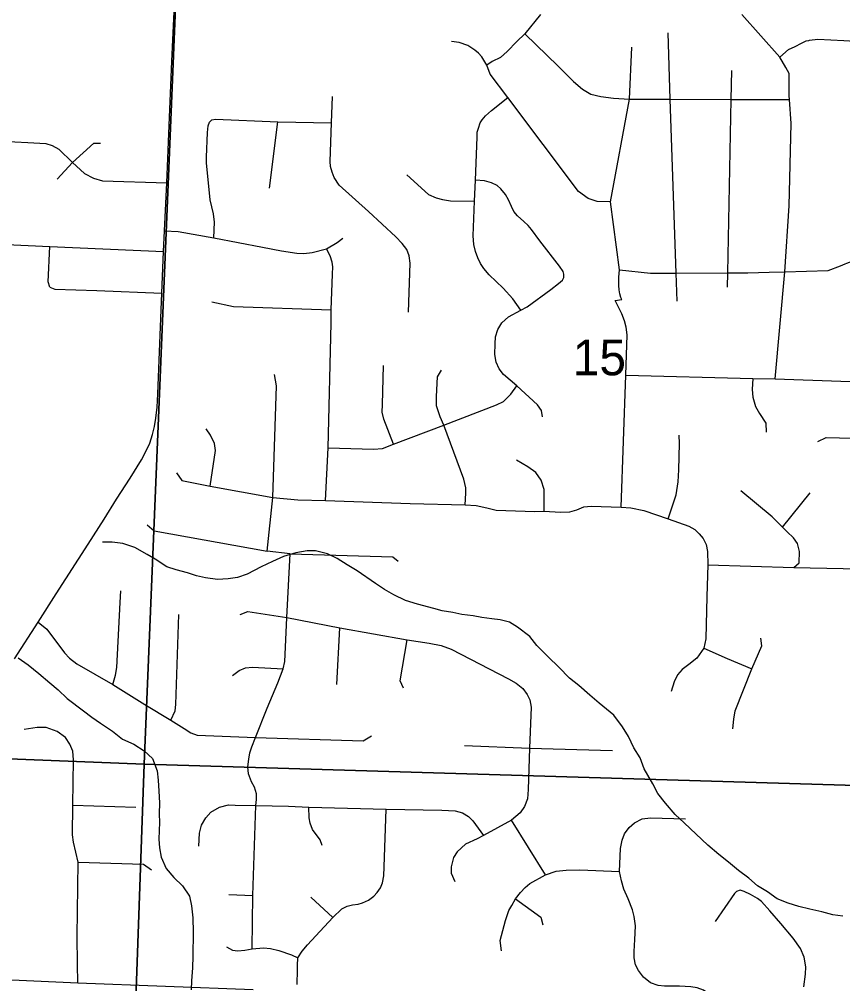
# Model space of a CAD drawing. Extents: x 0 to 34, y 0 to 22.
# Drawn here: x 6.135 to 7.099, y 17.654 to 18.784 of the extents above; entities that cross this region are included whole.
import ezdxf

# ---------------------------------------------------------------- set-up
doc = ezdxf.new("R2010")
doc.units = 0
for name, color, linetype in [('GM_X_Corporation', 7, 'Continuous'), ('GM_X_Minor_River', 7, 'Continuous'), ('GM_X_Section_Text', 7, 'Continuous'), ('GM_X_State_Route', 7, 'Continuous'), ('GM_X_Township_Road', 7, 'Continuous')]:
    doc.layers.add(name, color=color, linetype=linetype)

msp = doc.modelspace()

# ---------------------------------------------------------------- linework, layer by layer
at = {"layer": 'GM_X_Corporation'}
for points in [[(5.2829, 18.9603), (6.3228, 18.9214), (6.2808, 17.9117), (5.2412, 17.9526)], [(6.3228, 18.9214), (7.3448, 18.8879), (7.31, 17.8806), (6.2808, 17.9117)], [(5.2412, 17.9526), (6.2808, 17.9117), (6.2453, 16.9071), (5.2034, 16.9522)], [(7.31, 17.8806), (7.2756, 16.8704), (6.2453, 16.9071), (6.2808, 17.9117)]]:
    msp.add_lwpolyline(points, close=True, dxfattribs=at)
at = {"layer": 'GM_X_Minor_River'}
for points in [[(7.0991, 17.7334), (7.0873, 17.7352), (7.0743, 17.7384), (7.0603, 17.7416), (7.0473, 17.7449), (7.0348, 17.7489), (7.0222, 17.7536), (7.0107, 17.7618), (6.9992, 17.7689), (6.9888, 17.7779), (6.9766, 17.7868), (6.9651, 17.7969), (6.9536, 17.8059), (6.9409, 17.8167), (6.9132, 17.8429), (6.9028, 17.8527), (6.8913, 17.8658), (6.8824, 17.8771), (6.8766, 17.8884), (6.8665, 17.9061), (6.8617, 17.919), (6.8544, 17.9306), (6.8481, 17.9438), (6.8408, 17.9555), (6.8307, 17.969), (6.8138, 17.9829), (6.8027, 17.9926), (6.79, 18.0038), (6.7789, 18.0124), (6.7666, 18.0251), (6.7539, 18.0375), (6.7408, 18.0506), (6.7323, 18.0611), (6.7182, 18.072), (6.7086, 18.0779), (6.6976, 18.0808), (6.6881, 18.0818), (6.6763, 18.0835), (6.666, 18.0853), (6.6527, 18.087), (6.6421, 18.0891), (6.6299, 18.0912), (6.62, 18.0938), (6.6009, 18.0992), (6.5869, 18.1035), (6.5731, 18.1098), (6.5624, 18.1161), (6.5517, 18.1232), (6.5302, 18.1381), (6.5184, 18.1451), (6.5069, 18.1526), (6.4954, 18.1581), (6.4814, 18.1617), (6.4719, 18.1616), (6.4586, 18.1591), (6.4439, 18.1547), (6.4311, 18.1489), (6.4179, 18.1426), (6.4013, 18.134), (6.39, 18.1304), (6.3794, 18.1288), (6.3669, 18.1278), (6.3528, 18.1299), (6.3422, 18.1324), (6.3315, 18.1357), (6.3185, 18.1393), (6.3075, 18.1429), (6.2937, 18.1519), (6.2842, 18.1574), (6.27, 18.1656), (6.2559, 18.17), (6.2434, 18.1717), (6.232, 18.1715)], [(6.1333, 18.036), (6.1452, 18.0278), (6.1574, 18.0177), (6.1705, 18.0069), (6.1801, 17.9987), (6.1905, 17.9886), (6.21, 17.974), (6.2196, 17.9665), (6.2296, 17.9598), (6.2437, 17.9502), (6.2556, 17.9408), (6.2686, 17.9349), (6.2808, 17.9271), (6.2908, 17.9182), (6.2959, 17.9038), (6.2972, 17.8928), (6.2982, 17.8799), (6.2987, 17.8662), (6.2985, 17.8533), (6.2987, 17.8434), (6.2984, 17.8339), (6.2982, 17.8236), (6.2987, 17.8134), (6.3007, 17.8028), (6.3066, 17.7892), (6.3155, 17.7787), (6.3258, 17.7689), (6.334, 17.7569), (6.3364, 17.7455), (6.3377, 17.7315), (6.3383, 17.7148), (6.338, 17.6867)], [(6.338, 17.6867), (6.3374, 17.673), (6.3361, 17.6578), (6.3358, 17.6471)]]:
    msp.add_lwpolyline(points, dxfattribs=at)
at = {"layer": 'GM_X_State_Route'}
for points in [[(6.1291, 18.0348), (6.1567, 18.0779), (6.178, 18.1111), (6.2153, 18.1692), (6.2339, 18.1988), (6.2486, 18.2219), (6.2643, 18.2465), (6.2777, 18.2683), (6.2832, 18.2787), (6.2874, 18.2878), (6.2906, 18.2978), (6.293, 18.3073), (6.2946, 18.3168), (6.2961, 18.33), (6.2969, 18.3454), (6.2989, 18.3945), (6.3014, 18.4636), (6.3035, 18.5124), (6.3046, 18.5364), (6.3073, 18.5928), (6.3103, 18.6597), (6.3132, 18.7351), (6.3169, 18.8101)], [(6.048, 17.6624), (6.203, 17.6552), (6.4083, 17.6474)]]:
    msp.add_lwpolyline(points, dxfattribs=at)
at = {"layer": 'GM_X_Township_Road'}
for p, q in [((6.4276, 18.5865), (6.4375, 18.664)), ((7.0284, 18.1892), (7.0608, 18.2296)), ((6.4518, 18.1579), (6.425, 18.1613)), ((6.5065, 18.0049), (6.5098, 18.0715)), ((6.1973, 17.8635), (6.2712, 17.8613)), ((6.7507, 17.7821), (6.711, 17.8459)), ((6.3801, 17.759), (6.4082, 17.7576)), ((6.5017, 17.732), (6.476, 17.7559)), ((6.4604, 17.6705), (6.4605, 17.6756)), ((6.4599, 17.6534), (6.4604, 17.6705))]:
    msp.add_line(p, q, dxfattribs=at)
for points in [[(6.7451, 18.7901), (6.7265, 18.7673), (6.7173, 18.7581), (6.7059, 18.7465), (6.6982, 18.7396), (6.6882, 18.7348), (6.682, 18.7304)], [(7.0196, 18.3629), (7.031, 18.4885), (7.036, 18.5658), (7.0384, 18.6622), (7.0364, 18.6902), (7.0361, 18.6946), (7.0363, 18.7208), (7.0321, 18.7277), (7.0253, 18.7401), (6.9808, 18.7898)], [(6.827, 18.5704), (6.8112, 18.5708), (6.8008, 18.5745), (6.7896, 18.5825), (6.7067, 18.6926), (6.6861, 18.7202), (6.682, 18.7304), (6.6761, 18.7402), (6.6724, 18.7446), (6.668, 18.7483), (6.6599, 18.7536), (6.6497, 18.7571), (6.6407, 18.7583)], [(6.7265, 18.7673), (6.7658, 18.7295), (6.7835, 18.7114), (6.794, 18.7026), (6.804, 18.6965), (6.8155, 18.6937), (6.8303, 18.692), (6.8492, 18.6909), (6.8965, 18.6907), (6.9677, 18.6905), (7.0364, 18.6902)], [(6.8939, 18.7684), (6.8965, 18.6907), (6.9034, 18.487), (6.9045, 18.454)], [(7.0253, 18.7401), (7.0355, 18.749), (7.0431, 18.7523), (7.0507, 18.7563), (7.0561, 18.7592), (7.059, 18.7596), (7.06, 18.7597)], [(7.06, 18.7597), (7.0697, 18.7609), (7.1, 18.7596), (7.1661, 18.7557), (7.1991, 18.7493)], [(6.8393, 18.2126), (6.8449, 18.3673), (6.8464, 18.4147), (6.8453, 18.4237), (6.8434, 18.431), (6.8401, 18.4391), (6.8322, 18.4549), (6.8401, 18.4559), (6.8392, 18.4583), (6.838, 18.4625), (6.8371, 18.4672), (6.8366, 18.4724), (6.8365, 18.4782), (6.8368, 18.4822), (6.8376, 18.4909), (6.827, 18.5704), (6.8492, 18.6909), (6.852, 18.7517)], [(6.9684, 18.7243), (6.9677, 18.6905), (6.964, 18.4873), (6.9637, 18.4704)], [(6.5905, 18.4413), (6.5922, 18.4984), (6.5912, 18.507), (6.5883, 18.5144), (6.5831, 18.5216), (6.5757, 18.5293), (6.5435, 18.5592), (6.5092, 18.5901), (6.5034, 18.5989), (6.5009, 18.6051), (6.4992, 18.6118), (6.4988, 18.6176), (6.5001, 18.6631), (6.5015, 18.6938)], [(6.722, 18.4436), (6.7126, 18.4569), (6.7014, 18.4691), (6.685, 18.4849), (6.6786, 18.4922), (6.6748, 18.498), (6.6715, 18.5049), (6.6687, 18.5122), (6.6669, 18.5206), (6.6662, 18.5306), (6.6676, 18.5712), (6.669, 18.596), (6.6707, 18.6461), (6.6709, 18.6522), (6.6722, 18.6568), (6.6743, 18.6628), (6.6768, 18.6665), (6.6807, 18.6713), (6.6876, 18.6776), (6.7067, 18.6926)], [(6.3624, 18.5284), (6.3631, 18.5467), (6.362, 18.5565), (6.3582, 18.5726), (6.3538, 18.6163), (6.3538, 18.6229), (6.3552, 18.6515), (6.3557, 18.6595), (6.3572, 18.6637), (6.3601, 18.6665), (6.3645, 18.6673), (6.4375, 18.664), (6.5001, 18.6631)], [(5.7213, 18.6607), (5.7359, 18.6557), (5.8725, 18.6501), (6.0787, 18.6416), (6.1294, 18.6408), (6.1445, 18.64)], [(6.1445, 18.64), (6.1657, 18.6388), (6.1732, 18.6365), (6.1808, 18.6322), (6.1969, 18.6164), (6.211, 18.6035), (6.2216, 18.598), (6.2322, 18.5949), (6.3073, 18.5928)], [(6.179, 18.597), (6.1969, 18.6164), (6.2219, 18.6393), (6.2299, 18.6391)], [(6.5886, 18.6022), (6.6137, 18.5791), (6.6228, 18.575), (6.6303, 18.5731), (6.6397, 18.5716), (6.6676, 18.5712)], [(6.7474, 18.3184), (6.7462, 18.3258), (6.7416, 18.3327), (6.7172, 18.3548), (6.7017, 18.3683), (6.6967, 18.3746), (6.693, 18.3825), (6.6913, 18.3915), (6.6917, 18.4039), (6.6923, 18.4123), (6.6951, 18.4209), (6.6997, 18.4287), (6.7073, 18.4356), (6.722, 18.4436), (6.7292, 18.4473), (6.7569, 18.4677), (6.7662, 18.4748), (6.7706, 18.4786), (6.7722, 18.4819), (6.7723, 18.4855), (6.7714, 18.4888), (6.767, 18.4952), (6.7441, 18.5249), (6.7345, 18.538), (6.7305, 18.5427), (6.7256, 18.5475), (6.7181, 18.5542), (6.7139, 18.5591), (6.7109, 18.565), (6.7076, 18.5728), (6.7039, 18.5791), (6.6986, 18.5855), (6.6942, 18.5897), (6.6876, 18.5928), (6.6792, 18.595), (6.669, 18.596)], [(6.3046, 18.5364), (6.3207, 18.5358), (6.3624, 18.5284), (6.4193, 18.5174), (6.4417, 18.513), (6.4597, 18.5102), (6.4679, 18.51), (6.4775, 18.5112), (6.4944, 18.5154), (6.5067, 18.5229), (6.5134, 18.528)], [(5.8752, 18.5299), (5.97, 18.5272), (6.0601, 18.5232), (6.1705, 18.5179), (6.3035, 18.5124)], [(6.1704, 18.4706), (6.1684, 18.4768), (6.1705, 18.5179)], [(6.4932, 18.2205), (6.4963, 18.2823), (6.4998, 18.4282), (6.5, 18.444), (6.5015, 18.4858), (6.5018, 18.4942), (6.501, 18.4999), (6.4986, 18.5073), (6.4944, 18.5154)], [(7.0961, 18.4956), (7.1015, 18.4977), (7.1037, 18.4985), (7.1392, 18.512), (7.1407, 18.5133)], [(6.8376, 18.4909), (6.8736, 18.4869), (6.9034, 18.487), (6.964, 18.4873), (6.9879, 18.4874), (7.0126, 18.4879), (7.031, 18.4885), (7.0817, 18.4901), (7.0961, 18.4956)], [(6.1704, 18.4706), (6.1764, 18.4682), (6.2255, 18.4667), (6.3014, 18.4636)], [(6.3601, 18.4533), (6.3855, 18.4477), (6.5, 18.444)], [(6.573, 18.2865), (6.5616, 18.3157), (6.5596, 18.3239), (6.5599, 18.3328), (6.5611, 18.3787)], [(6.425, 18.1613), (6.4315, 18.2242), (6.4357, 18.3547), (6.4334, 18.3683)], [(6.6568, 18.2154), (6.6577, 18.229), (6.6577, 18.2354), (6.6551, 18.2453), (6.6317, 18.3088), (6.6275, 18.3186), (6.6232, 18.3316), (6.623, 18.3423), (6.6244, 18.3655), (6.6289, 18.3731)], [(6.8449, 18.3673), (6.9935, 18.3634), (7.0196, 18.3629), (7.1627, 18.3581)], [(6.9935, 18.3634), (6.9928, 18.3504), (6.9937, 18.3414), (6.9968, 18.3307), (7.0012, 18.3226), (7.0089, 18.3111), (7.0091, 18.3006)], [(6.4963, 18.2823), (6.5494, 18.2806), (6.5601, 18.2814), (6.573, 18.2865), (6.6317, 18.3088), (6.6934, 18.3327), (6.7015, 18.3364), (6.7101, 18.345), (6.7172, 18.3548)], [(6.3581, 18.2371), (6.3643, 18.2792), (6.3632, 18.2871), (6.3587, 18.2972), (6.3536, 18.3045)], [(6.8943, 18.1991), (6.9038, 18.227), (6.9063, 18.2423), (6.907, 18.2564), (6.9078, 18.2872), (6.9075, 18.297)], [(7.0697, 18.2896), (7.0795, 18.2945), (7.173, 18.2918)], [(6.7493, 18.2081), (6.7493, 18.2335), (6.7459, 18.2445), (6.7394, 18.2532), (6.7301, 18.26), (6.7169, 18.2676)], [(6.3189, 18.2529), (6.3249, 18.2439), (6.3581, 18.2371), (6.4315, 18.2242), (6.4608, 18.2211), (6.4932, 18.2205), (6.5922, 18.2171), (6.6568, 18.2154), (6.6695, 18.2146), (6.6822, 18.212), (6.6932, 18.2092), (6.7383, 18.2075), (6.7493, 18.2081), (6.7685, 18.207), (6.7792, 18.2072), (6.7874, 18.2095), (6.7958, 18.2129), (6.8043, 18.214), (6.8393, 18.2126), (6.8508, 18.212), (6.8661, 18.2086), (6.8943, 18.1991), (6.9185, 18.1905), (6.9256, 18.1864), (6.9309, 18.1815), (6.9356, 18.1758), (6.9391, 18.169), (6.9406, 18.1608), (6.9408, 18.1453), (6.9399, 18.108), (6.9385, 18.0585), (6.9363, 18.0475), (6.9281, 18.0356), (6.9185, 18.0282), (6.9109, 18.0223), (6.9054, 18.0163), (6.9015, 18.0082), (6.8978, 17.9967)], [(7.0417, 18.142), (7.048, 18.1473), (7.0481, 18.1609), (7.0458, 18.1701), (7.0411, 18.1768), (7.0338, 18.1839), (7.0284, 18.1892), (7.0163, 18.2012), (6.9796, 18.2317)], [(6.2845, 18.192), (6.2927, 18.185), (6.425, 18.1613)], [(6.4073, 17.6954), (6.4082, 17.7576), (6.4115, 17.8633), (6.4124, 17.8701), (6.4124, 17.8768), (6.41, 17.8848), (6.4066, 17.8908), (6.4029, 17.9002), (6.4024, 17.9084), (6.4033, 17.9175), (6.4046, 17.9247), (6.4068, 17.9317), (6.4113, 17.9427), (6.4248, 17.9773), (6.4373, 18.0067), (6.4437, 18.0232), (6.4456, 18.0318), (6.4473, 18.0658), (6.448, 18.0834), (6.4518, 18.1579)], [(6.4518, 18.1579), (6.5719, 18.1545), (6.5781, 18.1494)], [(6.9408, 18.1453), (7.0417, 18.142), (7.1379, 18.1402)], [(6.244, 18.0049), (6.2474, 18.0158), (6.2489, 18.0249), (6.2527, 18.101), (6.2534, 18.1148)], [(6.3121, 17.9631), (6.317, 17.974), (6.3181, 17.9813), (6.3213, 18.0869)], [(6.3931, 18.0868), (6.4022, 18.0903), (6.448, 18.0834), (6.5098, 18.0715), (6.5888, 18.0573), (6.6144, 18.0534), (6.6286, 18.0507), (6.6403, 18.0462), (6.7073, 18.0116), (6.7164, 18.0065), (6.7243, 18.0002), (6.7294, 17.9931), (6.7324, 17.987), (6.7339, 17.9782), (6.7319, 17.9305), (6.7304, 17.8817), (6.7296, 17.8708), (6.7262, 17.8621), (6.721, 17.8544), (6.711, 17.8459), (6.6783, 17.8281), (6.6708, 17.8239), (6.6572, 17.8177), (6.6475, 17.809), (6.643, 17.8023), (6.6403, 17.7913), (6.6405, 17.7839), (6.6445, 17.774)], [(6.1567, 18.0779), (6.1667, 18.0699), (6.1874, 18.0421), (6.1933, 18.0356), (6.2022, 18.0292), (6.244, 18.0049), (6.2816, 17.9813), (6.3121, 17.9631), (6.3275, 17.9533), (6.3354, 17.9482), (6.3428, 17.9456), (6.4113, 17.9427), (6.5371, 17.9389), (6.5472, 17.9447)], [(6.5845, 18.0007), (6.5806, 18.0091), (6.5888, 18.0573)], [(6.9702, 17.9529), (6.9715, 17.9644), (6.9727, 17.9742), (6.9923, 18.0233), (7.0042, 18.0503), (7.003, 18.0593)], [(6.9363, 18.0475), (6.9637, 18.0352), (6.9923, 18.0233)], [(6.3842, 18.0156), (6.3919, 18.0214), (6.3997, 18.0243), (6.4079, 18.0252), (6.4437, 18.0232)], [(6.203, 17.6552), (6.2027, 17.6774), (6.2023, 17.7101), (6.2034, 17.7966), (6.198, 17.8201), (6.1971, 17.8286), (6.1973, 17.8635), (6.1982, 17.9166), (6.1973, 17.9268), (6.194, 17.9351), (6.1889, 17.9427), (6.1791, 17.95), (6.166, 17.9544), (6.1555, 17.9544), (6.1402, 17.9522)], [(6.6559, 17.9333), (6.7319, 17.9305), (6.8292, 17.9275)], [(6.345, 17.8155), (6.3455, 17.8308), (6.3481, 17.8401), (6.353, 17.8488), (6.359, 17.8553), (6.369, 17.8613), (6.3795, 17.8639), (6.3873, 17.8637), (6.4115, 17.8633), (6.4498, 17.8622), (6.4738, 17.8612), (6.5643, 17.859), (6.6294, 17.8575), (6.645, 17.857), (6.6535, 17.8544), (6.6606, 17.8502), (6.6658, 17.8453), (6.6783, 17.8281)], [(6.4605, 17.6756), (6.4608, 17.6846), (6.466, 17.6923), (6.4722, 17.7), (6.4819, 17.7103), (6.5017, 17.732), (6.5125, 17.7419), (6.5185, 17.7452), (6.5249, 17.7467), (6.5314, 17.7476), (6.5365, 17.749), (6.5434, 17.7523), (6.5496, 17.7568), (6.5536, 17.7612), (6.5576, 17.7668), (6.5601, 17.7725), (6.5616, 17.7808), (6.5619, 17.7912), (6.5643, 17.859)], [(6.4891, 17.8161), (6.4871, 17.823), (6.478, 17.835), (6.4751, 17.8423), (6.474, 17.8488), (6.4738, 17.8612)], [(6.855, 17.6996), (6.8553, 17.7057), (6.856, 17.7221), (6.8548, 17.733), (6.8528, 17.7409), (6.8476, 17.7536), (6.8426, 17.7653), (6.8399, 17.7747), (6.8374, 17.7859), (6.8386, 17.8129), (6.8404, 17.8224), (6.8433, 17.8298), (6.8488, 17.8375), (6.855, 17.843), (6.8639, 17.8474), (6.8739, 17.8487), (6.9146, 17.8474)], [(6.2034, 17.7966), (6.2801, 17.7945), (6.2896, 17.7876)], [(6.6994, 17.6928), (6.6979, 17.7049), (6.7041, 17.7285), (6.708, 17.7402), (6.7113, 17.7459), (6.7157, 17.7536), (6.7215, 17.7613), (6.7269, 17.767), (6.7326, 17.7717), (6.7507, 17.7821), (6.7632, 17.7861), (6.7751, 17.7874), (6.791, 17.7876), (6.8374, 17.7859)], [(7.0531, 17.6507), (7.0553, 17.6657), (7.0555, 17.6741), (7.0538, 17.6854), (7.0494, 17.6957), (7.0409, 17.7079), (7.0262, 17.7248), (7.0135, 17.7398), (7.0037, 17.7506), (6.9992, 17.7543), (6.9908, 17.759), (6.9835, 17.7625), (6.9788, 17.7639), (6.9746, 17.7625), (6.972, 17.76), (6.9495, 17.7271)], [(6.7157, 17.7536), (6.7455, 17.7322), (6.7475, 17.7233)], [(6.3771, 17.6974), (6.3841, 17.6936), (6.3904, 17.6929), (6.3988, 17.6936), (6.4073, 17.6954), (6.4206, 17.6962), (6.4286, 17.6956), (6.4386, 17.6931), (6.4535, 17.688), (6.4608, 17.6846)], [(6.9445, 17.5068), (6.9511, 17.5219), (6.9521, 17.5292), (6.9546, 17.585), (6.9553, 17.6143), (6.9543, 17.6213), (6.9516, 17.6292), (6.9474, 17.6362), (6.9419, 17.6424), (6.9357, 17.6469), (6.9282, 17.6496), (6.9208, 17.6508), (6.9076, 17.6516), (6.89, 17.6516), (6.8828, 17.6523), (6.8739, 17.6555), (6.8654, 17.662), (6.8597, 17.6697), (6.8563, 17.6764), (6.8545, 17.6846), (6.8548, 17.6915), (6.855, 17.6996)]]:
    msp.add_lwpolyline(points, dxfattribs=at)

# ---------------------------------------------------------------- texts
at = {"layer": 'GM_X_Section_Text'}
msp.add_text('15', height=0.04186, rotation=0, dxfattribs=at).set_placement((6.7828, 18.3672))

doc.saveas('drawing.dxf')
